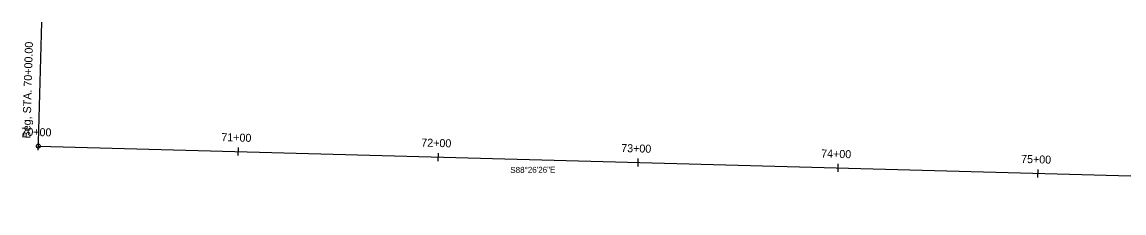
# Model space of a CAD drawing. Extents: x 925213 to 926427, y 852880 to 858734.
# Drawn here: x 925213 to 925764, y 853473 to 853568 of the extents above; entities that cross this region are included whole.
import ezdxf

# ---------------------------------------------------------------- set-up
doc = ezdxf.new("R2010")
doc.units = 0
for name, color, linetype in [('BaselineSurvey', 7, 'Continuous'), ('CurveDataLabel_dp', 7, 'Continuous'), ('Default', 7, 'Continuous'), ('StationTicL_dp', 7, 'Continuous'), ('TextBLStation', 7, 'Continuous'), ('TextCurveData', 7, 'Continuous')]:
    doc.layers.add(name, color=color, linetype=linetype)

# ---------------------------------------------------------------- blocks, each defined once
blk = doc.blocks.new('FDOTStationTicL')
at = {"layer": 'StationTicL_dp'}
blk.add_line((0, -0.5), (0, 0.5), dxfattribs=at)
blk = doc.blocks.new('AeccTickCircle')
at = {"layer": 'Default'}
blk.add_circle((0, 0), 1, dxfattribs=at)

msp = doc.modelspace()

# ---------------------------------------------------------------- linework, layer by layer
at = {"layer": 'BaselineSurvey'}
msp.add_lwpolyline([(925221.62, 853506.01), (925841.39, 853489.14), (925948.17, 853486.23), (926421.16, 853472.64)], dxfattribs=at)
at = {"layer": 'CurveDataLabel_dp'}
msp.add_line((925221.67, 853508.01), (925223.3, 853567.99), dxfattribs=at)

# ---------------------------------------------------------------- block references
at = {"layer": 'CurveDataLabel_dp', "rotation": -1.5594444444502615}
msp.add_blockref('AeccTickCircle', (925221.62, 853506.01), dxfattribs=at)
at = {"layer": 'TextBLStation', "xscale": 4, "yscale": 4, "rotation": -1.5594444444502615}
for p in [(925221.62, 853506.01), (925321.58, 853503.29), (925421.54, 853500.57), (925521.5, 853497.85), (925621.47, 853495.13), (925721.43, 853492.41)]:
    msp.add_blockref('FDOTStationTicL', p, dxfattribs=at)

# ---------------------------------------------------------------- texts
at = {"layer": 'CurveDataLabel_dp'}
msp.add_text('Beg, STA. 70+00.00', height=4, rotation=88.4406, dxfattribs=at).set_placement((925217.61, 853509.82))
at = {"layer": 'TextBLStation'}
for s, p in [('70+00', (925213.09, 853511.26)), ('71+00', (925313.06, 853508.53)), ('72+00', (925413.02, 853505.81)), ('73+00', (925512.98, 853503.09)), ('74+00', (925612.95, 853500.37)), ('75+00', (925712.91, 853497.65))]:
    msp.add_text(s, height=4, rotation=358.4406, dxfattribs=at).set_placement(p)
at = {"layer": 'TextCurveData'}
msp.add_text('S88°26\'26"E', height=3, rotation=0.3378, dxfattribs=at).set_placement((925457.58, 853492.61))

doc.saveas('drawing.dxf')
